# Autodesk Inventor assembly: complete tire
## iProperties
Author: vincent molino
Shininess: 64.0
Angle Display Precision: 2
Document Length Units: 11272
Document Angle Units: 11286
Document Time Units: 11279
Document Mass Units: 11290
Document Length Units Precision: 3
Document Angle Units Precision: 2
Compacted: True
PropertySet Name: _Private Model Information
Created: 2002-01
Part Number: complete tire
Document SubType Name: Assembly
Designer: vincent molino
Control State: 0
Master: False
Checked Out: False
PropertySet Name: Design Tracking Control
Density: 0.0
Volumn: 0.0
Area: 0.0
PropertySet Name: Model Information
